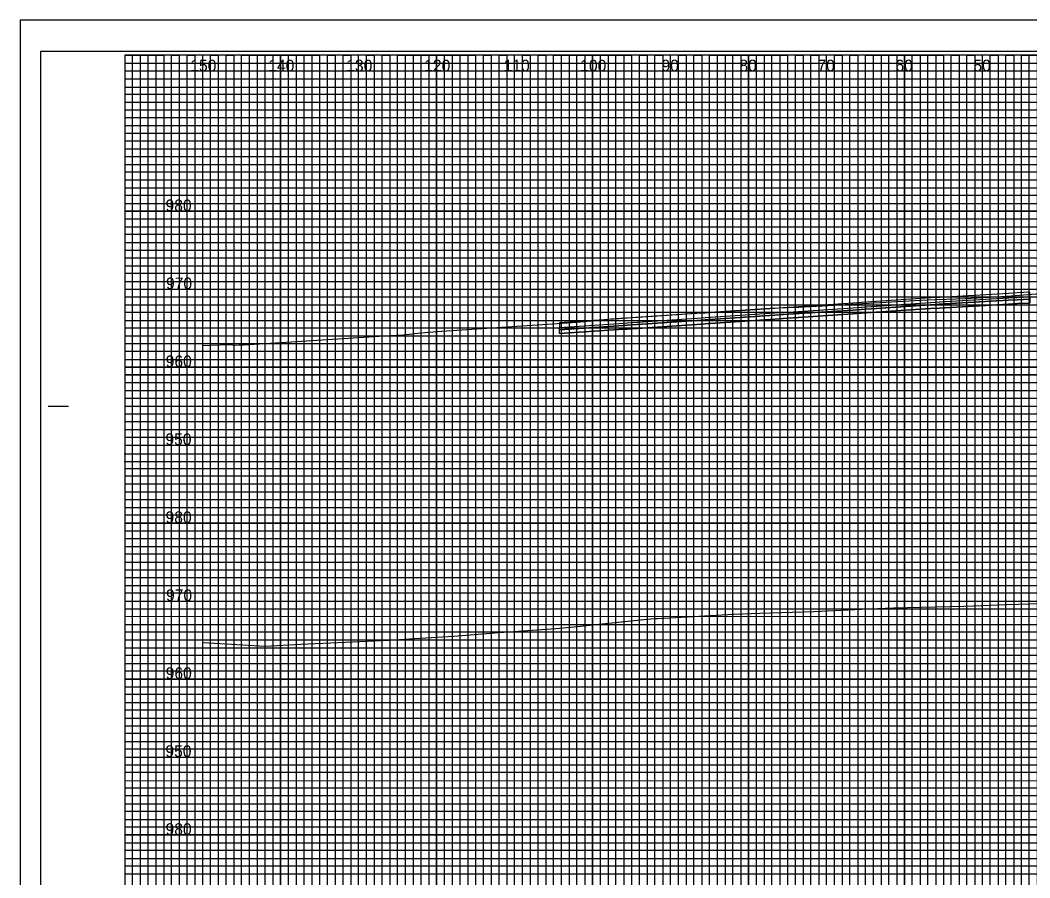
# Model space of a CAD drawing. Extents: x -13 to 760, y -5 to 1491.
# Drawn here: x -13.4 to 116.1, y 423.5 to 533.5 of the extents above; entities that cross this region are included whole.
import ezdxf

# ---------------------------------------------------------------- set-up
doc = ezdxf.new("R2010")
doc.units = 0
for name, color, linetype in [('Default', 7, 'Continuous'), ('Exist XS Ground Line', 7, 'Continuous'), ('Prop CMT Pvmt Course 3', 7, 'Continuous'), ('Prop CMT Pvmt Course 4', 7, 'Continuous'), ('Prop CMT Subgrade Earthwork', 7, 'Continuous'), ('Prop Conc Curb and Gutter', 7, 'Continuous'), ('Prop XS Elevation Labels', 7, 'Continuous'), ('Prop XS Offset Labels', 7, 'Continuous'), ('Sheet Cross Section CELL', 7, 'Continuous'), ('Sheet Cross Section Grid Major CELL', 7, 'Continuous'), ('Sheet Cross Section Grid Middle CELL', 7, 'Continuous'), ('Sheet Cross Section Grid Minor 1 CELL', 7, 'Continuous'), ('Sheet Cross Section Grid Minor 2 CELL', 7, 'Continuous'), ('Sheet Cutting Line CELL', 7, 'Continuous'), ('Sheet DOT Grid CELL', 7, 'Continuous'), ('Sheet Plot Border Inside CELL', 7, 'Continuous'), ('Sheet Plot Border Outside CELL', 7, 'Continuous')]:
    doc.layers.add(name, color=color, linetype=linetype)

msp = doc.modelspace()

# ---------------------------------------------------------------- linework, layer by layer
at = {"layer": 'Exist XS Ground Line'}
for points in [[(10, 491.79), (10.01, 491.79), (10.96, 491.82), (13.54, 491.91), (14.13, 491.84), (14.7, 491.85), (15.24, 491.88), (19.33, 492.13), (33.97, 493.05), (35.76, 493.16), (37.92, 493.39), (40.66, 493.6), (58.04, 494.76), (59.83, 494.94), (62.33, 495.2), (80.24, 496.39), (82.77, 496.57), (85.05, 496.67), (86.43, 496.71), (101.31, 497.57), (102.96, 497.63), (107.77, 497.81), (110.86, 498), (113.13, 498.11), (119.01, 498.57)], [(10, 491.79), (10.01, 491.79), (10.96, 491.82), (13.54, 491.91), (14.13, 491.84), (14.7, 491.85), (15.24, 491.88), (19.33, 492.13), (33.97, 493.05), (35.76, 493.16), (37.92, 493.39), (40.66, 493.6), (58.04, 494.76), (59.83, 494.94), (62.33, 495.2), (80.24, 496.39), (82.77, 496.57), (85.05, 496.67), (86.43, 496.71), (101.31, 497.57), (102.96, 497.63), (107.77, 497.81), (110.86, 498), (113.13, 498.11), (119.01, 498.57)], [(10, 453.67), (10.8, 453.64), (18.03, 453.21), (22.57, 453.49), (33.95, 454), (37.17, 454.22), (42.19, 454.49), (47.41, 454.94), (55.27, 455.5), (57.64, 455.68), (66.13, 456.58), (67.88, 456.76), (68.36, 456.78), (78.11, 457.32), (81.45, 457.44), (88.35, 457.67), (94.53, 457.97), (98.58, 458.15), (107.62, 458.35), (108.82, 458.37), (113.11, 458.54), (119.05, 458.75)], [(10, 453.67), (10.8, 453.64), (18.03, 453.21), (22.57, 453.49), (33.95, 454), (37.17, 454.22), (42.19, 454.49), (47.41, 454.94), (55.27, 455.5), (57.64, 455.68), (59.16, 455.85), (66.13, 456.58), (67.88, 456.76), (68.36, 456.78), (78.11, 457.32), (81.45, 457.44), (88.35, 457.67), (94.53, 457.97), (98.58, 458.15), (107.62, 458.35), (108.82, 458.37), (113.11, 458.54), (119.05, 458.75)]]:
    msp.add_lwpolyline(points, dxfattribs=at)
at = {"layer": 'Prop CMT Pvmt Course 3'}
msp.add_lwpolyline([(55.74, 494.1), (63.35, 494.61), (64.44, 494.68), (73.35, 495.28), (74.44, 495.36), (83.35, 495.95), (84.44, 496.03), (93.35, 496.63), (94.44, 496.7), (103.35, 497.3), (103.38, 497.3), (104.44, 497.36), (113.35, 497.89), (114.44, 497.94), (116.06, 498.01), (116.06, 497.72), (114.44, 497.65), (113.35, 497.6), (104.44, 497.07), (103.38, 497.01), (103.35, 497.01), (94.44, 496.41), (93.35, 496.33), (84.44, 495.74), (83.35, 495.66), (74.44, 495.06), (73.35, 494.99), (64.44, 494.39), (63.35, 494.32), (55.74, 493.81), (55.74, 494.1)], dxfattribs=at)
at = {"layer": 'Prop CMT Pvmt Course 4'}
msp.add_lwpolyline([(55.74, 493.81), (63.35, 494.32), (64.44, 494.39), (73.35, 494.99), (74.44, 495.06), (83.35, 495.66), (84.44, 495.74), (93.35, 496.33), (94.44, 496.41), (103.35, 497.01), (103.38, 497.01), (104.44, 497.07), (113.35, 497.6), (114.44, 497.65), (116.06, 497.72), (116.06, 497.22), (114.44, 497.15), (113.35, 497.1), (104.44, 496.57), (103.38, 496.51), (103.35, 496.51), (94.44, 495.91), (93.35, 495.83), (84.44, 495.24), (83.35, 495.16), (74.44, 494.56), (73.35, 494.49), (64.44, 493.89), (63.35, 493.82), (55.74, 493.31), (55.74, 493.81)], dxfattribs=at)
at = {"layer": 'Prop CMT Subgrade Earthwork'}
msp.add_lwpolyline([(55.74, 493.31), (63.35, 493.82), (64.44, 493.89), (73.35, 494.49), (74.44, 494.56), (83.35, 495.16), (84.44, 495.24), (93.35, 495.83), (94.44, 495.91), (103.35, 496.51), (103.38, 496.51), (104.44, 496.57), (113.35, 497.1), (114.44, 497.15), (116.06, 497.22)], dxfattribs=at)
at = {"layer": 'Prop Conc Curb and Gutter'}
msp.add_lwpolyline([(55.74, 494.1), (55.74, 494.1), (55.75, 494.1), (63.35, 494.61), (63.35, 494.61), (64.44, 494.68), (64.47, 494.69), (73.35, 495.28), (73.35, 495.28), (74.44, 495.36), (74.48, 495.36), (83.35, 495.95), (83.35, 495.95), (84.44, 496.03), (84.5, 496.03), (93.35, 496.63), (93.35, 496.63), (94.44, 496.7), (94.51, 496.7), (103.35, 497.3), (103.35, 497.3), (103.38, 497.3), (103.39, 497.3), (104.44, 497.36), (104.53, 497.37), (113.35, 497.89), (113.36, 497.89), (114.44, 497.94), (114.46, 497.94), (116.06, 498.01), (116.06, 498.02), (116.06, 498.6), (114.46, 498.52), (114.44, 498.52), (113.36, 498.47), (113.35, 498.47), (104.55, 497.95), (104.44, 497.95), (103.39, 497.88), (103.38, 497.88), (103.35, 497.88), (103.35, 497.88), (94.53, 497.29), (94.44, 497.28), (93.36, 497.21), (93.35, 497.21), (84.51, 496.62), (84.44, 496.61), (83.35, 496.54), (83.35, 496.54), (74.49, 495.94), (74.44, 495.94), (73.35, 495.87), (73.35, 495.87), (64.47, 495.27), (64.44, 495.27), (63.35, 495.19), (63.35, 495.19), (55.75, 494.68), (55.74, 494.68), (55.74, 494.1)], dxfattribs=at)
at = {"layer": 'Sheet Cross Section CELL'}
for p, q in [((-9.8, 484), (-7.3, 484)), ((-9.7, 484), (-7.2, 484))]:
    msp.add_line(p, q, dxfattribs=at)
msp.add_lwpolyline([(320, 529), (0, 529), (0, 319), (320, 319)], close=True, dxfattribs=at)
at = {"layer": 'Sheet Cross Section Grid Major CELL'}
for p, q in [((10, 529), (0, 529)), ((10, 319), (10, 529)), ((30, 529), (20, 529)), ((20, 529), (20, 319)), ((30, 319), (30, 529)), ((50, 529), (40, 529)), ((40, 529), (40, 319)), ((50, 319), (50, 529)), ((70, 529), (60, 529)), ((60, 529), (60, 319)), ((70, 319), (70, 529)), ((90, 529), (80, 529)), ((80, 529), (80, 319)), ((90, 319), (90, 529)), ((110, 529), (100, 529)), ((100, 529), (100, 319)), ((110, 319), (110, 529))]:
    msp.add_line(p, q, dxfattribs=at)
for points in [[(0, 519), (320, 519), (320, 509), (0, 509)], [(0, 499), (320, 499), (320, 489), (0, 489)], [(0, 479), (320, 479), (320, 469), (0, 469)], [(0, 459), (320, 459), (320, 449), (0, 449)], [(0, 439), (320, 439), (320, 429), (0, 429)]]:
    msp.add_lwpolyline(points, dxfattribs=at)
at = {"layer": 'Sheet Cross Section Grid Middle CELL'}
for points in [[(0, 529), (5, 529), (5, 319)], [(15, 319), (15, 529), (25, 529), (25, 319)], [(35, 319), (35, 529), (45, 529), (45, 319)], [(55, 319), (55, 529), (65, 529), (65, 319)], [(75, 319), (75, 529), (85, 529), (85, 319)], [(95, 319), (95, 529), (105, 529), (105, 319)], [(115, 319), (115, 529), (125, 529), (125, 319)], [(0, 524), (275, 524)], [(0, 504), (320, 504), (320, 514), (0, 514)], [(0, 484), (320, 484), (320, 494), (0, 494)], [(0, 464), (320, 464), (320, 474), (0, 474)], [(0, 444), (320, 444), (320, 454), (0, 454)], [(0, 424), (320, 424), (320, 434), (0, 434)]]:
    msp.add_lwpolyline(points, dxfattribs=at)
at = {"layer": 'Sheet Cross Section Grid Minor 1 CELL'}
for p, q in [((0, 528), (260, 528)), ((260, 526.98), (0, 526.98)), ((0, 526.98), (0, 526)), ((0, 526), (260, 526)), ((260, 524.89), (0, 524.89)), ((0, 524.89), (0, 523)), ((0, 523), (320, 523))]:
    msp.add_line(p, q, dxfattribs=at)
for points in [[(0, 522), (270, 522), (320, 522), (320, 521), (0, 521)], [(0, 520), (320, 520), (320, 518), (0, 518)], [(0, 517), (320, 517), (320, 516), (0, 515.98)], [(0, 515), (320, 515), (320, 513), (0, 513)], [(0, 512), (320, 512), (320, 511), (0, 511)], [(0, 510), (320, 510), (320, 508), (0, 508)], [(0, 507), (320, 507), (320, 506), (0, 506)], [(0, 505), (320, 505), (320, 503), (0, 503)], [(0, 502), (320, 502), (320, 501), (0, 501)], [(0, 500), (320, 500), (320, 498), (0, 498)], [(0, 497), (320, 497), (320, 496), (0, 496)], [(0, 495), (320, 495), (320, 492.95), (320, 492), (320, 491), (0, 491)], [(0, 493), (320, 493), (320, 492), (0, 492)], [(0, 490), (320, 490), (320, 488), (0, 488.03)], [(0, 488.03), (320, 488), (320, 487), (0, 487)], [(0, 486), (320, 486), (320, 485), (0, 485)], [(0, 483), (320, 483), (320, 482), (0, 482)], [(0, 481), (320, 481), (320, 480), (0, 480)], [(-0.07, 477.89), (320, 477.89), (320, 476.88), (-0.07, 476.88)], [(0, 476), (320, 476), (320, 475), (0, 475)], [(0, 473), (320, 473), (320, 472), (0, 472)], [(0, 471), (320, 471), (320, 470), (0, 470)], [(0, 468), (320, 468), (320, 467), (0, 467)], [(0, 466), (320, 466), (320, 465), (0, 465)], [(0, 463), (320, 463), (320, 462), (0, 462)], [(0, 461), (320, 461), (320, 460), (0, 460)], [(0, 458), (320, 458), (319.99, 456.98), (0, 457)], [(0, 456), (320, 456), (320, 455), (0, 455)], [(0, 453), (320, 453), (320, 452), (0, 452)], [(0, 451), (320, 451), (320, 450), (0, 450)], [(0, 448), (320, 448), (320, 447), (0, 447)], [(0, 446), (320, 446), (320, 445), (0, 445)], [(0, 443), (320, 443), (320, 442), (0, 442)], [(0, 441), (320, 441), (320, 440), (0, 440)], [(0, 438), (320, 438), (320, 437), (0, 437)], [(0, 435.99), (320.07, 435.91), (320, 435), (0, 435)], [(0, 433), (320, 433), (320, 432), (0, 432)], [(0, 431), (320, 431), (320, 430), (0, 430)], [(0, 428), (320, 428), (320, 427), (0, 427)], [(0, 426), (320, 426), (320, 425), (0, 425)]]:
    msp.add_lwpolyline(points, dxfattribs=at)
at = {"layer": 'Sheet Cross Section Grid Minor 2 CELL'}
for points in [[(0, 319), (1, 319), (1, 529), (2, 529), (2, 319)], [(2, 319), (3, 319), (3, 529), (4, 529), (4, 319)], [(5, 319), (6, 319), (6, 529), (7, 529), (7, 319)], [(7, 319), (8, 319), (8, 529), (9, 529), (9, 319)], [(10, 319), (11, 319), (11, 529), (12, 529), (12, 319)], [(12, 319), (13, 319), (13, 529), (14, 529), (14, 319)], [(15, 319), (16, 319), (16, 529), (17, 529), (17, 319)], [(17, 319), (18, 319), (18, 529), (19, 529), (19, 319)], [(20, 319), (21, 319), (21, 529), (22, 529), (22, 319)], [(22, 319), (23, 319), (23, 529), (24, 529), (24, 319)], [(25, 319), (26, 319), (26, 529), (27, 529), (27, 319)], [(27, 319), (28, 319), (28, 529), (29, 529), (29, 319)], [(30, 319), (31, 319), (31, 529), (32, 529), (32, 319)], [(32, 319), (33, 319), (33, 529), (34, 529), (34, 319)], [(35, 319), (36, 319), (36, 529), (37, 529), (37, 319)], [(37, 319), (38, 319), (38, 529), (39, 529), (39, 319)], [(40, 319), (41, 319), (41, 529), (42, 529), (42, 319)], [(42, 319), (43, 319), (43, 529), (44, 529), (44, 319)], [(45, 319), (46, 319), (46, 529), (47, 529), (47, 319)], [(47, 319), (48, 319), (48, 529), (49, 529), (49, 319)], [(50, 319), (51, 319), (51, 529), (52, 529), (52, 319)], [(52, 319), (53, 319), (53, 529), (54, 529), (54, 319)], [(55, 319), (56, 319), (56, 529), (57, 529), (57, 319)], [(57, 319), (58, 319), (58, 529), (59, 529), (59, 319)], [(60, 319), (61, 319), (61, 529), (62, 529), (62, 319)], [(62, 319), (63, 319), (63, 529), (64, 529), (64, 319)], [(65, 319), (66, 319), (66, 529), (67, 529), (67, 319)], [(67, 319), (68, 319), (68, 529), (69, 529), (69, 319)], [(70, 319), (71, 319), (71, 529), (72, 529), (72, 319)], [(72, 319), (73, 319), (73, 529), (74, 529), (74, 319)], [(75, 319), (76, 319), (76, 529), (77, 529), (77, 319)], [(77, 319), (78, 319), (78, 529), (79, 529), (79, 319)], [(80, 319), (81, 319), (81, 529), (82, 529), (82, 319)], [(82, 319), (83, 319), (83, 529), (84, 529), (84, 319)], [(85, 319), (86, 319), (86, 529), (87, 529), (87, 319)], [(87, 319), (88, 319), (88, 529), (89, 529), (89, 319)], [(90, 319), (91, 319), (91, 529), (92, 529), (92, 319)], [(92, 319), (93, 319), (93, 529), (94, 529), (94, 319)], [(95, 319), (96, 319), (96, 529), (97, 529), (97, 319)], [(97, 319), (98, 319), (98, 529), (99, 529), (99, 319)], [(100, 319), (101, 319), (101, 529), (102, 529), (102, 319)], [(102, 319), (103, 319), (103, 529), (104, 529), (104, 319)], [(105, 319), (106, 319), (106, 529), (107, 529), (107, 319)], [(107, 319), (108, 319), (108, 529), (109, 529), (109, 319)], [(110, 319), (111, 319), (111, 529), (112, 529), (112, 319)], [(112, 319), (113, 319), (113, 529), (114, 529), (114, 319)], [(115, 319), (116, 319), (116, 529), (117, 529), (117, 319)]]:
    msp.add_lwpolyline(points, dxfattribs=at)
at = {"layer": 'Sheet Cutting Line CELL'}
for p, q in [((323.3, 533.5), (-13.4, 533.5)), ((-13.4, 533.5), (-13.4, 314.5))]:
    msp.add_line(p, q, dxfattribs=at)
at = {"layer": 'Sheet DOT Grid CELL'}
for p, q in [((10, 319), (10, 529)), ((20, 319), (20, 529)), ((30, 319), (30, 529)), ((40, 319), (40, 529)), ((50, 319), (50, 529)), ((60, 319), (60, 529)), ((70, 319), (70, 529)), ((80, 319), (80, 529)), ((90, 319), (90, 529)), ((100, 319), (100, 529)), ((110, 319), (110, 529)), ((0, 519), (320, 519)), ((0, 509), (320, 509)), ((0, 499), (320, 499)), ((0, 489), (320, 489)), ((0, 479), (320, 479)), ((0, 469), (320, 469)), ((0, 459), (320, 459)), ((0, 449), (320, 449)), ((0, 439), (320, 439)), ((0, 429), (320, 429))]:
    msp.add_line(p, q, dxfattribs=at)
at = {"layer": 'Sheet Plot Border Inside CELL'}
msp.add_lwpolyline([(-10.8, 318.5), (322.4, 318.5), (322.4, 529.5), (-10.8, 529.5)], close=True, dxfattribs=at)
at = {"layer": 'Sheet Plot Border Outside CELL'}
msp.add_lwpolyline([(-13.4, 314.5), (323.3, 314.5), (323.3, 533.5), (-13.4, 533.5)], close=True, dxfattribs=at)

# ---------------------------------------------------------------- texts
at = {"layer": 'Default'}
for p in [(10, 479), (10, 439)]:
    msp.add_text('-', height=0.0001, dxfattribs=at).set_placement(p)
at = {"layer": 'Prop XS Elevation Labels'}
for s, p in [('980', (5.24, 509)), ('970', (5.3, 499)), ('960', (5.26, 489)), ('950', (5.22, 479)), ('980', (5.24, 469)), ('970', (5.3, 459)), ('960', (5.26, 449)), ('950', (5.22, 439)), ('980', (5.24, 429))]:
    msp.add_text(s, height=1.5, dxfattribs=at).set_placement(p)
at = {"layer": 'Prop XS Offset Labels'}
for s, p in [('150', (8.41, 526.94)), ('140', (18.41, 526.94)), ('130', (28.41, 526.94)), ('120', (38.41, 526.94)), ('110', (48.59, 526.94)), ('100', (58.41, 526.94)), ('90', (68.83, 526.94)), ('80', (78.83, 526.94)), ('70', (88.83, 526.94)), ('60', (98.83, 526.94)), ('50', (108.83, 526.94))]:
    msp.add_text(s, height=1.5, dxfattribs=at).set_placement(p)

doc.saveas('drawing.dxf')
